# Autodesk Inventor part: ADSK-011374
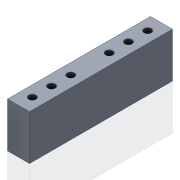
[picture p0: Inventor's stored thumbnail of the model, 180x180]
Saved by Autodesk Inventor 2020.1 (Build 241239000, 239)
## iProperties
Created: 1999-12
Part Number: ADSK-011374
Material: Pearson Aluminium
Description: PLT-09,FA,CP,07,026,051,BLOCK,MNT,TIMING_BELT
Document SubType Name: Modeling
Designer: sspink
Density: 2.71 g/cm^3
Appearance: Pearson-Aluminum
Mass: 269.925 g
Surface Area: 217.256 cm^2
Volume: 99.6033 cm^3
Control State: 0
Checked Out: False
Master: False
Shininess: 35.0
Length Units: 11269
Angle Units: 11279
Time Units: 11290
Mass Units: 11283
Length Display Precision: 3
Angle Display Precision: 2
Compacted: True
Dimensions: 20x41x130,2 mm
Mass: 0,27 kg
DocNumber: ADSK-011357.ipt
Folder: 01 - Themengebiete\Simplification\01 - Packaging machine\
VDS_Category: 3D Komponenten
Density: 2.71
Volumn: 154.09010176277914
Area: 305.3057301923691
PropertySet Name: Model Information
Author: sspink
Revision Number: -
Title: PLT-09,FA,CP,07,026,051,BLOCK,MNT,TIMING_BELT
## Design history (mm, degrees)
node "Hole1" dims "d10" = 6.647, "d11" = 9.525, "d12" = 6.35, "d13" = 60 deg, "d14" = 22.2, "d15" = 118 deg, "d38" = 16
  sketch "Sketch2"
    geometry: L1 (0, 0)-(0, 130.175) reference; L2 (0, 0)-(20, 0) reference; L3 (10, 111.088)-(10, 19.087); 4 further points
    constraints: 3 midpoint, 3 vertical alignment, 2 end point, 1 coincident, 1 horizontal alignment, 1 vertical
    dimensions: "d37" = 92 distance of L3.end L3.start
sketch "Sketch3"
  geometry: L1 (20, 0)-(0, 0) reference; L2 (0, 0)-(0, -130.175) reference; L3 (10, -12.588)-(10, -117.587); L4 (20, 0)-(20, -130.175) reference; 5 further points
  constraints: 4 vertical alignment, 3 midpoint, 2 end point, 1 horizontal alignment, 1 parallel
  dimensions: "d39" = 105 distance of L3.start L3.end; "d40" = 35 distance of L3.start point (10, -47.588) (= 0.333333 x d39); "d41" = 35 distance of L3.end point (10, -82.587) (= 0.333333 x d39)
node "Hole2" dims "d22" = 6.647, "d23" = 9.525, "d24" = 6.35, "d25" = 60 deg, "d26" = 22.2, "d27" = 118 deg, "d42" = 16
sketch "Sketch4"
  geometry: L1 (20, 0)-(0, 0) reference; L2 (0, 0)-(0, -130.175) reference; L3 (10, -30.088)-(10, -100.087); 3 further points
  constraints: 3 midpoint, 2 end point, 2 vertical alignment, 1 horizontal alignment, 1 parallel
  dimensions: "d43" = 70 distance of L3.end L3.start
node "Hole3" dims "d31" = 6.647, "d32" = 9.525, "d33" = 6.35, "d34" = 60 deg, "d35" = 22.2, "d36" = 118 deg, "d44" = 16
node "Solide1"
  node "Extrusion1" dims "d4" = 130.175, "d5" = 0
sketch "Sketch1"
  geometry: L1 (-10, -20.5)-(10, -20.5); L2 (10, -20.5)-(10, 20.5); L3 (10, 20.5)-(-10, 20.5); L4 (-10, 20.5)-(-10, -20.5); 3 further points
  constraints: 8 end point, 2 midpoint, 2 parallel, 1 horizontal, 1 horizontal alignment, 1 perpendicular, 1 vertical alignment
  dimensions: "d0" = 20 distance between parallel lines of L2 L4; "d3" = 41 distance of L1.end L2.end
node "Corps solides"
node "Corps surfaciques"
